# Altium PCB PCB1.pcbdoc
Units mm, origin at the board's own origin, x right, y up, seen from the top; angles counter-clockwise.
Board outline 153.8 x 97.66 mm, 2 copper layers (Top Layer, Bottom Layer); 80 components, 110 nets, 410 pads, 304 vias.
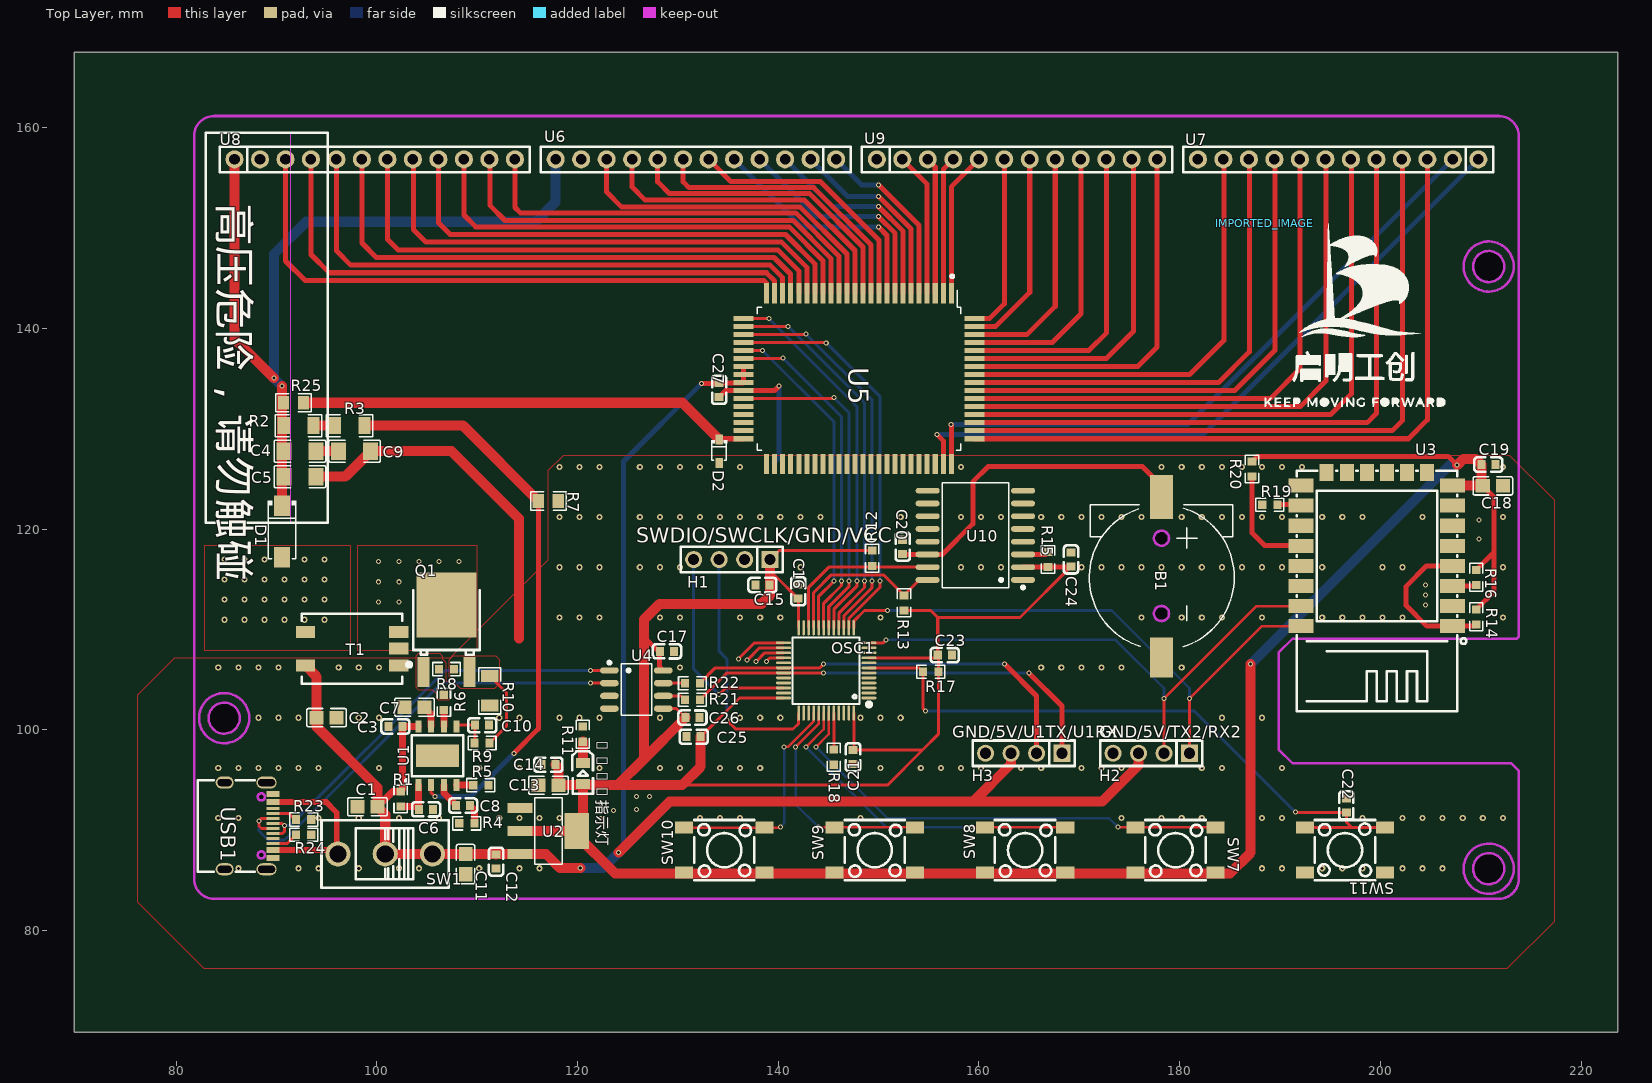
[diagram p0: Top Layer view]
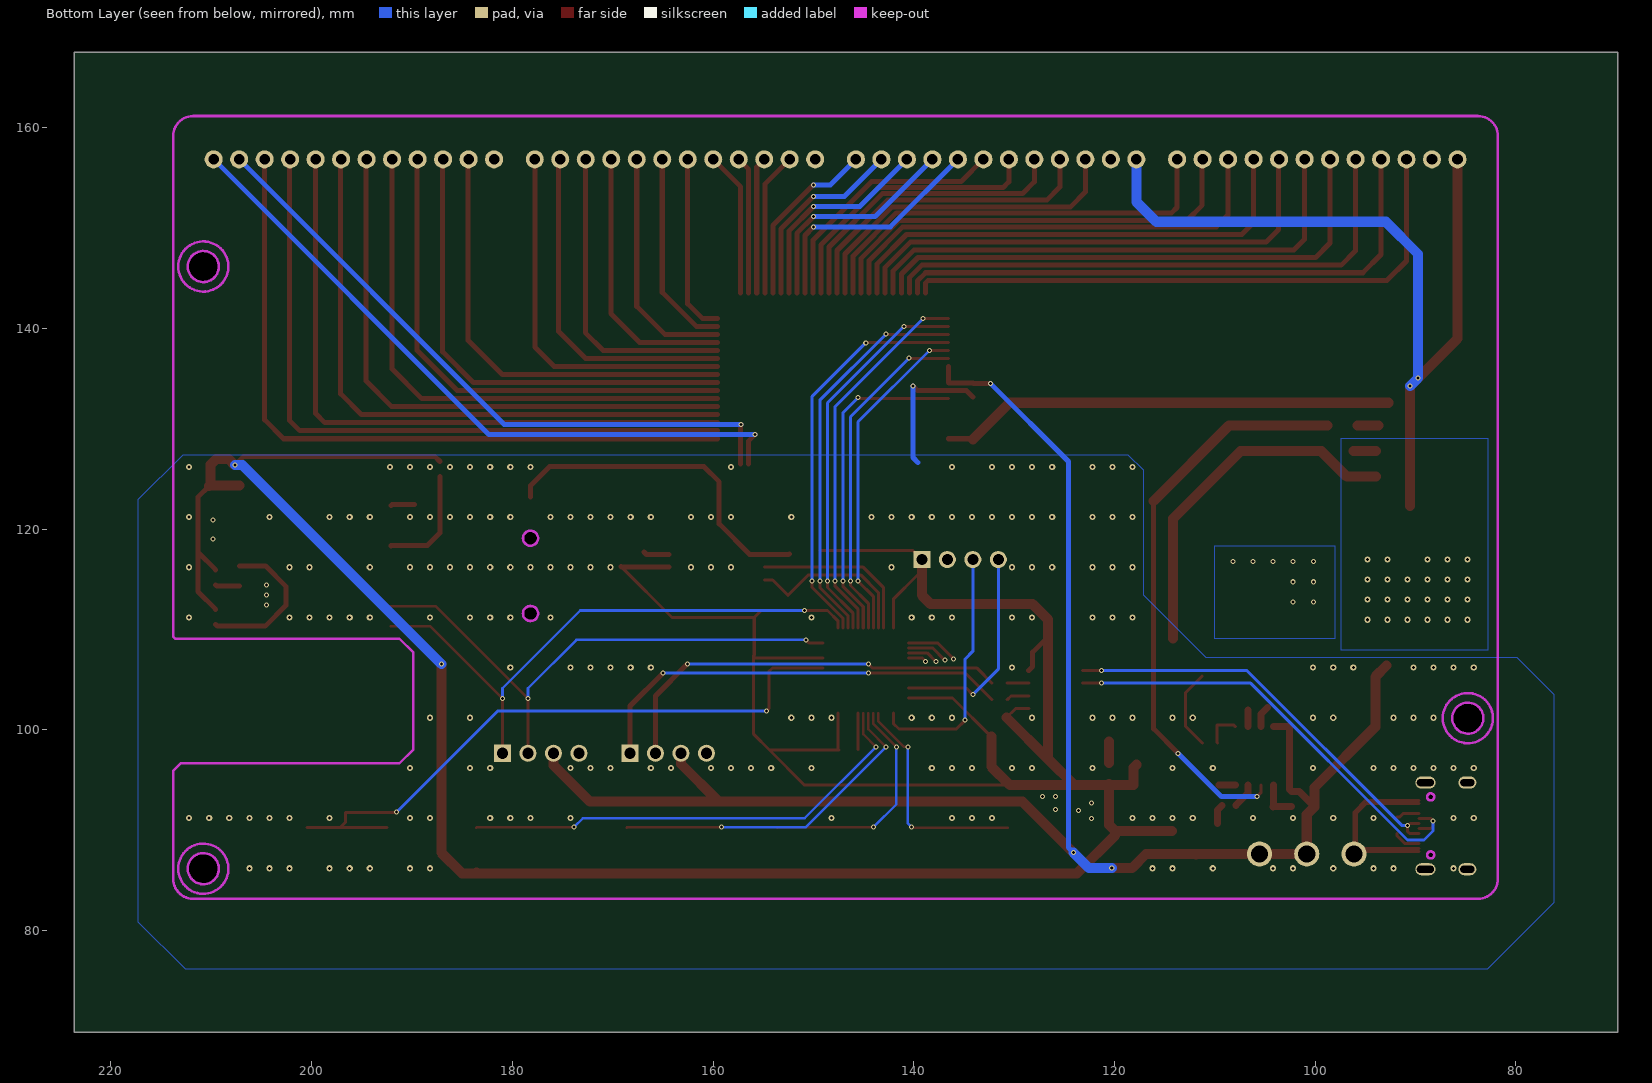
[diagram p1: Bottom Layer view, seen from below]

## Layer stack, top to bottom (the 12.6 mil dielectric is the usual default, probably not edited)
Top Layer: signal copper (thickness not stored)
Dielectric: dielectric 0.32, FR-4, Dk 4.8
Bottom Layer: signal copper (thickness not stored)

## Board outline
223.647,69.85 69.85,69.85 69.85,167.513 223.647,167.513
cut-out: 86.338,101.163 ccw(c84.788,101.151) 83.238,101.163 ccw(c84.788,101.175)
cut-out: 212.338,146.163 ccw(c210.788,146.151) 209.238,146.163 ccw(c210.788,146.175)
cut-out: 212.338,86.163 ccw(c210.788,86.151) 209.238,86.163 ccw(c210.788,86.175)

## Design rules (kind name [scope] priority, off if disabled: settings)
Clearance copperThickness1oz [All] p1: gap=0.178 ignorepadtopadclearanceinfootprint=FALSE except(0.102: Track-Track; 0.152: Track-SMDPad SMDPad-SMDPad Track-THPad SMDPad-THPad THPad-THPad Track-Via SMDPad-Via THPad-Via Via-Via Track-Fill SMDPad-Fill THPad-Fill Via-Fill Fill-Fill Track-Region SMDPad-Region THPad-Region Via-Region Fill-Region Region-Region Track-Poly SMDPad-Poly THPad-Poly Via-Poly Fill-Poly Region-Poly Poly-Poly Track-Text SMDPad-Text THPad-Text Via-Text Fill-Text Region-Text Poly-Text Text-Text Track-Hole SMDPad-Hole THPad-Hole Via-Hole Fill-Hole Region-Hole Poly-Hole Text-Hole; 0.3: Track-Sheet SMDPad-Sheet THPad-Sheet Via-Sheet Fill-Sheet Region-Sheet Poly-Sheet Text-Sheet Sheet-Hole)
Clearance copperThickness2oz [All] p1: gap=0.178 ignorepadtopadclearanceinfootprint=FALSE except(0.152: Track-SMDPad SMDPad-SMDPad Track-THPad SMDPad-THPad THPad-THPad Track-Via SMDPad-Via THPad-Via Via-Via Track-Fill SMDPad-Fill THPad-Fill Via-Fill Fill-Fill Track-Region SMDPad-Region THPad-Region Via-Region Fill-Region Region-Region Track-Poly SMDPad-Poly THPad-Poly Via-Poly Fill-Poly Region-Poly Poly-Poly Track-Text SMDPad-Text THPad-Text Via-Text Fill-Text Region-Text Poly-Text Text-Text Track-Hole SMDPad-Hole THPad-Hole Via-Hole Fill-Hole Region-Hole Poly-Hole Text-Hole; 0.203: Track-Track; 0.3: Track-Sheet SMDPad-Sheet THPad-Sheet Via-Sheet Fill-Sheet Region-Sheet Poly-Sheet Text-Sheet Sheet-Hole)
DiffPairsRouting differentialPair [All] p1: maxuncoupledlength=10 maxlimit=5.9843 mostfreqgap=5.9843 toplayer_minwidth=5 toplayer_prefwidth=10 toplayer_maxwidth=100 bottomlayer_minwidth=5 bottomlayer_prefwidth=10 bottomlayer_maxwidth=100
PasteMaskExpansion pasteMaskExpansion [All] p1:
PlaneConnect innerPlane [All] p1: planeconnectstyle=Relief reliefexpansion=0.508 reliefentries=4 reliefconductorwidth=0.254 reliefairgap=0.254
PolygonConnect copperRegion [All] p1: connectstyle=Direct reliefentries=4 reliefconductorwidth=10 polygonreliefangle="90 Angle" airgapwidth=10
RoutingVias viaSize [All] p1: viastyle="Through Hole" holewidth=12.0078 minholewidth=11.811 maxholewidth=248.0314 width=24.0158 minwidth=19.685 maxwidth=393.7008
SolderMaskExpansion solderMaskExpansion [All] p1: useseparateexpansions=TRUE expansion=2.0079 expansionbottom=2.0079
Width copperThickness1oz [All] p1: maxlimit=100 minlimit=5 preferedwidth=10
Width copperThickness2oz [All] p1: maxlimit=100 minlimit=8 preferedwidth=10

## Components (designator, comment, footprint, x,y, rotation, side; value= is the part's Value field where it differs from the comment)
3.3V指示灯 "NCD0805R1" LED0805-R-RD 120.523,95.631 r270 top
B1 "CR1220-2" BAT-SMD_CR1220-2 178.181,115.189 r270 top
C1 "0805X106K250NT" C0805 99.06,92.329 r0 top
C2 "0805X106K250NT" C0805 94.996,101.219 r180 top
C3 "0603B104K500NT" C0603 101.854,100.33 r0 top
C4 "CL31B105KCHNNNE" C1206 92.329,127.762 r180 top
C5 "1206B104K251NT_C2909525" C1206 92.329,125.222 r180 top
C6 "0603B104K500NT" C0603 104.902,92.075 r180 top
C7 "0805X106K250NT" C0805 103.759,102.235 r180 top
C8 "0603B103K500NT" C0603 108.585,92.456 r180 top
C9 "CL31B105KCHNNNE" C1206 97.79,127.762 r180 top
C10 "0603B104K500NT" C0603 110.49,100.457 r180 top
C11 "GRM21BR61H106KE43L" C0805 108.839,86.614 r90 top
C12 "0603B104K500NT" C0603 111.887,86.868 r90 top
C13 "GRM21BR61H106KE43L" C0805 117.094,94.488 r0 top
C14 "0603B104K500NT" C0603 117.094,96.52 r0 top
C15 "0603B104K500NT" C0603 138.43,114.427 r0 top
C16 "0603B104K500NT" C0603 141.986,113.792 r270 top
C17 "0603B104K500NT" C0603 128.905,107.823 r180 top
C18 "0805X106K250NT" C0805 211.201,124.301 r180 top
C19 "0603B104K500NT" C0603 210.758,126.427 r0 top
C20 "0603B104K500NT" C0603 152.4,118.237 r270 top
C21 "0603B104K500NT" C0603 147.447,97.282 r90 top
C22 "0603B105K250NT" C0603 196.596,92.456 r270 top
C23 "0603B104K500NT" C0603 156.591,107.442 r0 top
C24 "0603B104K500NT" C0603 169.164,116.967 r270 top
C25 "0603B104K500NT" C0603 131.572,99.314 r180 top
C26 "0603B104K500NT" C0603 131.445,101.219 r180 top
C27 "0603B104K500NT" C0603 134.112,133.858 r270 top
D1 "ES1J_C412438" SMA_L4.4-W2.8-LS5.4-RD 90.551,119.761 r270 top
D2 "MM3Z68_C118625" SOD-323_L1.8-W1.3-LS2.5-RD-1 134.112,127.762 r270 top
H1 "PZ254V-11-04P" HDR-TH_4P-P2.54-V-M 135.382,116.967 r180 top
H2 "PZ254V-11-04P" HDR-TH_4P-P2.54-V-M 177.165,97.663 r180 top
H3 "PZ254V-11-04P" HDR-TH_4P-P2.54-V-M 164.465,97.663 r180 top
IMPORTED_IMAGE "IMPORTED_IMAGE" IMPORTED_IMAGE 188.468,150.495 r0 top
OSC1 "STM32F103C8T6TR" LQFP-48_L7.0-W7.0-P0.50-LS9.0-BL 144.78,105.918 r90 top
Q1 "NCEP02515K" TO-252-3_L6.6-W6.1-P4.58-LS10.1-BR-2 106.934,109.093 r270 top
R1 "0603WAF1002T5E" R0603 102.371,93.1 r90 top
R2 "1206W4F1003T5E" R1206 92.202,130.302 r0 top
R3 "1206W4F1003T5E" R1206 97.282,130.302 r0 top
R4 "0603WAF1002T5E" R0603 108.966,90.678 r0 top
R5 "0603WAF2002T5E" R0603 110.363,94.488 r180 top
R6 "0603WAF0000T5E" R0603 106.68,102.743 r90 top
R7 "0805W8F1501T5E" R0805 117.094,122.809 r180 top
R8 "0603WAF1002T5E" R0603 106.934,106.045 r180 top
R9 "0603WAF200JT5E" R0603 110.49,98.679 r0 top
R10 "1206W4F100LT5E" R1206 111.252,103.886 r90 top
R11 "0603WAF1001T5E" R0603 120.523,99.568 r270 top
R12 "0603WAF1002T5E" R0603 149.352,117.094 r90 top
R13 "0603WAF1002T5E" R0603 152.527,112.649 r270 top
R14 "0603WAF1002T5E" R0603 209.55,111.252 r90 top
R15 "0603WAF1002T5E" R0603 166.878,116.967 r90 top
R16 "0603WAF1002T5E" R0603 209.55,115.189 r90 top
R17 "0603WAF1002T5E" R0603 155.194,105.791 r180 top
R18 "0603WAF1002T5E" R0603 145.533,97.273 r90 top
R19 "0603WAF1002T5E" R0603 188.976,122.428 r180 top
R20 "0603WAF1002T5E" R0603 187.198,125.984 r270 top
R21 "0603WAF0000T5E" R0603 131.445,102.997 r0 top
R22 "0603WAF0000T5E" R0603 131.445,104.648 r0 top
R23 "RC0603FR-071KL" R0603 92.71,91.059 r0 top
R24 "RC0603FR-071KL" R0603 92.71,89.535 r0 top
R25 "0805W8F2403T5E" R0805 91.694,132.588 r180 top
SW1 "SS-12D10L3" SW-TH_SS-12D10L3 100.838,87.63 r180 top
SW7 "TS-1102S-B-A-B" SW-SMD_4P-L6.0-W6.0-P4.50-LS8.6 179.578,88.011 r0 top
SW8 "TS-1102S-B-A-B" SW-SMD_4P-L6.0-W6.0-P4.50-LS8.6 164.592,88.011 r0 top
SW9 "TS-1102S-B-A-B" SW-SMD_4P-L6.0-W6.0-P4.50-LS8.6 149.606,88.011 r0 top
SW10 "TS-1102S-B-A-B" SW-SMD_4P-L6.0-W6.0-P4.50-LS8.6 134.62,88.011 r0 top
SW11 "TS-1102S-B-A-B" SW-SMD_4P-L6.0-W6.0-P4.50-LS8.6 196.469,88.011 r180 top
T1 "TTRN-060S-013-T" TTRN-060S-013 97.536,108.077 r90 top
U1 "ASP3756" ESOP-8_L4.9-W3.9-P1.27-LS6.0-BL-EP4.2 106.045,97.409 r0 top
U2 "AMS1117-3.3_C369933" SOT-223-4_L6.5-W3.5-P2.30-LS7.0-BR 117.094,89.916 r180 top
U3 "ESP-12F(ESP8266MOD)" WIFIM-SMD_ESP-12F-ESP8266MOD 199.644,117.983 r90 top
U4 "CH340N" SOP-8_L4.9-W3.9-P1.27-LS6.0-BL 125.857,104.013 r270 top
U5 "HV57708" PQFP-80_L20.0-W14.0-P0.80-LS23.2-BL 148.042,135.001 r180 top
U6 "KH-2.54FH-1X12P-H8.5" HDR-TH_12P-P2.54-V-F 131.788,156.845 r180 top
U7 "KH-2.54FH-1X12P-H8.5" HDR-TH_12P-P2.54-V-F 195.788,156.845 r180 top
U8 "KH-2.54FH-1X12P-H8.5" HDR-TH_12P-P2.54-V-F 99.788,156.845 r0 top
U9 "KH-2.54FH-1X12P-H8.5" HDR-TH_12P-P2.54-V-F 163.788,156.845 r0 top
U10 "DS3231SN#T&R" SOIC-16_L10.3-W7.5-P1.27-LS10.3-BL 159.639,119.38 r90 top
USB1 "KH-TYPE-C-16P" USB-C-SMD_KH-TYPE-C-16P 87.249,90.424 r270 top

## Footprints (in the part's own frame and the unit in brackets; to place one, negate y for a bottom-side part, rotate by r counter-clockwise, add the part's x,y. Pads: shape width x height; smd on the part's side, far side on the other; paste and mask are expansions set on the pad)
BAT-SMD_CR1220-2 [mm]
  rect 4.4x2.3 smd: 1(-8,0)
  rect 4x2.3 smd: 2(8,0)
  Multi-Layer board cut-out: 3.6,0.75 3.275,0.676 3.014,0.468 2.869,0.167 2.869,-0.167 3.014,-0.468 3.275,-0.676 3.6,-0.75 3.6,-0.75 3.925,-0.676 4.186,-0.468 4.331,-0.167 4.331,0.167 4.186,0.468 3.925,0.676 3.6,0.75
  Multi-Layer board cut-out: -3.9,0.75 -4.225,0.676 -4.486,0.468 -4.631,0.167 -4.631,-0.167 -4.486,-0.468 -4.225,-0.676 -3.9,-0.75 -3.9,-0.75 -3.574,-0.676 -3.314,-0.468 -3.169,-0.167 -3.169,0.167 -3.314,0.468 -3.574,0.676 -3.9,0.75
  Multi-Layer keep-out circle w0.254: c3.6,0 r0.75
  Multi-Layer keep-out circle w0.254: c-3.9,0 r0.75
  silkscreen extent -7.22,-7.19 6.92,7.25
C0603 [mm]
  rect 0.8x0.9 smd: 1(-0.7,0) 2(0.7,0)
  silkscreen extent -1.41,-0.71 1.39,0.72
C0805 [mm]
  rect 1.41x1.35 smd: 1(-1,0) 2(1,0)
  silkscreen extent -1.96,-0.9 1.96,0.9
C1206 [mm]
  rect 1.485x1.728 smd: 1(-1.593,0) 2(1.593,0)
  silkscreen extent -2.56,-1.09 2.56,1.09
ESOP-8_L4.9-W3.9-P1.27-LS6.0-BL-EP4.2 [mm]
  rect 0.6x1.2 smd: 1(-1.905,-2.908) 2(-0.635,-2.908) 3(0.635,-2.908) 4(1.905,-2.908) 5(1.905,2.908) 6(0.635,2.908) 7(-0.635,2.908) 8(-1.905,2.908)
  rect 4.25x2.25 smd: 9(0,0)
  silkscreen extent -3.2,-2.67 2.55,2.05
HDR-TH_4P-P2.54-V-M [mm]
  rect 1.7x1.7 hole 1.1: 1(-3.81,0)
  round 1.7 hole 1.1: 2(-1.27,0) 3(1.27,0) 4(3.81,0)
  silkscreen extent -5.08,-1.27 5.08,1.27
HDR-TH_12P-P2.54-V-F [mm]
  round 1.8 hole 1.05: 1(-13.97,0) 2(-11.43,0) 3(-8.89,0) 4(-6.35,0) 5(-3.81,0) 6(-1.27,0) 7(1.27,0) 8(3.81,0) 9(6.35,0) 10(8.89,0) 11(11.43,0) 12(13.97,0)
  silkscreen extent -15.45,-1.27 15.45,1.27
IMPORTED_IMAGE [mm]
  silkscreen extent 0,-18.31 18,0
LED0805-R-RD [mm]
  rect 1x1.4 smd: 1(1.05,0) 2(-1.05,0)
  silkscreen extent -2.22,-1.04 1.99,1.01
LQFP-48_L7.0-W7.0-P0.50-LS9.0-BL [mm]
  oval 0.27x1.5 smd: 1(-2.75,-4.25) 2(-2.25,-4.25) 3(-1.75,-4.25) 4(-1.25,-4.25) 5(-0.75,-4.25) 6(-0.25,-4.25) 7(0.25,-4.25) 8(0.75,-4.25) 9(1.25,-4.25) 10(1.75,-4.25) 11(2.25,-4.25) 12(2.75,-4.25) 25(2.75,4.25) 26(2.25,4.25) 27(1.75,4.25) 28(1.25,4.25) 29(0.75,4.25) 30(0.25,4.25) 31(-0.25,4.25) 32(-0.75,4.25) 33(-1.25,4.25) 34(-1.75,4.25) 35(-2.25,4.25) 36(-2.75,4.25)
  oval 1.5x0.27 smd: 13(4.25,-2.75) 14(4.25,-2.25) 15(4.25,-1.75) 16(4.25,-1.25) 17(4.25,-0.75) 18(4.25,-0.25) 19(4.25,0.25) 20(4.25,0.75) 21(4.25,1.25) 22(4.25,1.75) 23(4.25,2.25) 24(4.25,2.75) 37(-4.25,2.75) 38(-4.25,2.25) 39(-4.25,1.75) 40(-4.25,1.25) 41(-4.25,0.75) 42(-4.25,0.25) 43(-4.25,-0.25) 44(-4.25,-0.75) 45(-4.25,-1.25) 46(-4.25,-1.75) 47(-4.25,-2.25) 48(-4.25,-2.75)
  silkscreen extent -3.59,-4.46 3.3,3.34
PQFP-80_L20.0-W14.0-P0.80-LS23.2-BL [mm]
  rect 0.5x2 smd: 1(-9.2,-8.5) 2(-8.4,-8.5) 3(-7.6,-8.5) 4(-6.8,-8.5) 5(-6,-8.5) 6(-5.2,-8.5) 7(-4.4,-8.5) 8(-3.6,-8.5) 9(-2.8,-8.5) 10(-2,-8.5) 11(-1.2,-8.5) 12(-0.4,-8.5) 13(0.4,-8.5) 14(1.2,-8.5) 15(2,-8.5) 16(2.8,-8.5) 17(3.6,-8.5) 18(4.4,-8.5) 19(5.2,-8.5) 20(6,-8.5) 21(6.8,-8.5) 22(7.6,-8.5) 23(8.4,-8.5) 24(9.2,-8.5) 41(9.2,8.5) 42(8.4,8.5) 43(7.6,8.5) 44(6.8,8.5) 45(6,8.5) 46(5.2,8.5) 47(4.4,8.5) 48(3.6,8.5) 49(2.8,8.5) 50(2,8.5) 51(1.2,8.5) 52(0.4,8.5) 53(-0.4,8.5) 54(-1.2,8.5) 55(-2,8.5) 56(-2.8,8.5) 57(-3.6,8.5) 58(-4.4,8.5) 59(-5.2,8.5) 60(-6,8.5) 61(-6.8,8.5) 62(-7.6,8.5) 63(-8.4,8.5) 64(-9.2,8.5)
  rect 2x0.5 smd: 25(11.5,-6) 26(11.5,-5.2) 27(11.5,-4.4) 28(11.5,-3.6) 29(11.5,-2.8) 30(11.5,-2) 31(11.5,-1.2) 32(11.5,-0.4) 33(11.5,0.4) 34(11.5,1.2) 35(11.5,2) 36(11.5,2.8) 37(11.5,3.6) 38(11.5,4.4) 39(11.5,5.2) 40(11.5,6) 65(-11.5,6) 66(-11.5,5.2) 67(-11.5,4.4) 68(-11.5,3.6) 69(-11.5,2.8) 70(-11.5,2) 71(-11.5,1.2) 72(-11.5,0.4) 73(-11.5,-0.4) 74(-11.5,-1.2) 75(-11.5,-2) 76(-11.5,-2.8) 77(-11.5,-3.6) 78(-11.5,-4.4) 79(-11.5,-5.2) 80(-11.5,-6)
  silkscreen extent -10.12,-10.35 10.12,7.13
R0603 [mm]
  rect 0.806x0.864 smd: 1(-0.753,0) 2(0.753,0)
  silkscreen extent -1.39,-0.66 1.39,0.66
R0805 [mm]
  rect 1.133x1.377 smd: 1(-1,0) 2(1,0)
  silkscreen extent -1.76,-0.92 1.76,0.92
R1206 [mm]
  rect 1.208x1.701 smd: 1(-1.479,0) 2(1.479,0)
  silkscreen extent -2.31,-1.08 2.31,1.08
SMA_L4.4-W2.8-LS5.4-RD [mm]
  rect 2.046x1.62 smd: 1(-2.565,0) 2(2.565,0)
  silkscreen extent -3.08,-1.44 2.7,1.44
SOD-323_L1.8-W1.3-LS2.5-RD-1 [mm]
  rect 1x0.75 smd: 1(-1.173,0) 2(1.173,0)
  silkscreen extent -1.08,-0.8 0.9,0.8
SOIC-16_L10.3-W7.5-P1.27-LS10.3-BL [mm]
  oval 0.574x2.401 smd: 1(-4.445,-4.75) 2(-3.175,-4.75) 3(-1.905,-4.75) 4(-0.635,-4.75) 5(0.635,-4.75) 6(1.905,-4.75) 7(3.175,-4.75) 8(4.445,-4.75) 9(4.445,4.75) 10(3.175,4.75) 11(1.905,4.75) 12(0.635,4.75) 13(-0.635,4.75) 14(-1.905,4.75) 15(-3.175,4.75) 16(-4.445,4.75)
  silkscreen extent -5.33,-4.9 5.23,3.32
SOP-8_L4.9-W3.9-P1.27-LS6.0-BL [mm]
  oval 0.63x1.865 smd: 1(-1.905,-2.682) 2(-0.635,-2.682) 3(0.635,-2.682) 4(1.905,-2.682) 5(1.905,2.682) 6(0.635,2.682) 7(-0.635,2.682) 8(-1.905,2.682)
  silkscreen extent -2.82,-2.83 2.58,1.52
SOT-223-4_L6.5-W3.5-P2.30-LS7.0-BR [mm]
  rect 2.47x0.98 smd: 1(2.835,-2.3) 2(2.835,0) 3(2.835,2.3)
  rect 2.47x3.6 smd: 4(-2.835,0)
  silkscreen extent -1.37,-3.33 1.37,3.33
SW-SMD_4P-L6.0-W6.0-P4.50-LS8.6 [mm]
  rect 1.8x1.2 smd: 1(-4,2.25) 2(4,2.25) 3(-4,-2.25) 4(4,-2.25)
  silkscreen extent -3,-3 3,3
SW-TH_SS-12D10L3 [mm]
  round 2.5 hole 1.7: 1(-4.7,0) 2(0,0) 3(4.7,0)
  silkscreen extent -6.35,-3.35 6.35,3.35
TO-252-3_L6.6-W6.1-P4.58-LS10.1-BR-2 [mm]
  rect 3x1.2 smd: 1(3.342,-2.285) 3(3.342,2.285)
  rect 6.5x6 smd: 2(-3.343,0)
  silkscreen extent -4.83,-3.92 2.81,3.3
TTRN-060S-013 [mm]
  rect 1.2x1.9 smd: 1(-1.675,4.65) 2(1.675,4.651) 3(-1.675,-4.65) 5(1.675,-4.651)
  rect 1.15x1.9 smd: EMPTY(0.025,-4.65)
  silkscreen extent -3.5,-5 3.5,5
USB-C-SMD_KH-TYPE-C-16P [mm]
  oval 1.2x2 hole 0.7 slot 1.7 at 90 deg: 1(-4.32,1.765) 2(4.32,1.765)
  oval 1.2x1.8 hole 0.7 slot 1.4 at 90 deg: 3(-4.32,-2.415) 4(4.32,-2.415)
  rect 0.3x1.3 smd: A1(-3.35,2.415) A4(-2.55,2.415) A5(-1.25,2.415) A6(-0.25,2.415) A7(0.25,2.415) A8(1.25,2.415) A9(2.55,2.415) A12(3.35,2.415) B1(3.05,2.415) B4(2.25,2.415) B5(1.75,2.415) B6(0.75,2.415) B7(-0.75,2.415) B8(-1.75,2.415) B9(-2.25,2.415) B12(-3.05,2.415)
  Multi-Layer board cut-out: -2.89,1.585 -3.042,1.55 -3.164,1.453 -3.231,1.313 -3.231,1.157 -3.164,1.017 -3.042,0.92 -2.89,0.885 -2.89,0.885 -2.738,0.92 -2.616,1.017 -2.549,1.157 -2.549,1.313 -2.616,1.453 -2.738,1.55 -2.89,1.585
  Multi-Layer board cut-out: 2.89,1.585 2.738,1.55 2.616,1.453 2.549,1.313 2.549,1.157 2.616,1.017 2.738,0.92 2.89,0.885 2.89,0.885 3.042,0.92 3.164,1.017 3.231,1.157 3.231,1.313 3.164,1.453 3.042,1.55 2.89,1.585
  Multi-Layer keep-out circle w0.254: c-2.89,1.235 r0.35
  Multi-Layer keep-out circle w0.254: c2.89,1.235 r0.35
  silkscreen extent -4.57,-5.08 4.57,0.57
WIFIM-SMD_ESP-12F-ESP8266MOD [mm]
  rect 1.4x2.5 smd: 1(-7.651,-7.551) 2(-5.651,-7.551) 3(-3.651,-7.551) 4(-1.651,-7.551) 5(0.349,-7.551) 6(2.349,-7.551) 7(4.349,-7.551) 8(6.349,-7.551) 9(6.349,7.549) 10(4.349,7.55) 11(2.349,7.551) 12(0.349,7.551) 13(-1.651,7.55) 14(-3.651,7.551) 15(-5.651,7.55) 16(-7.651,7.551)
  rect 1.7x1.4 smd: 17(7.651,-5) 18(7.649,-3.002) 19(7.65,-1.003) 20(7.65,0.997) 21(7.65,2.997) 22(7.65,4.997)
  silkscreen extent -16.15,-8.92 7.85,8

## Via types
v1: diameter 0.61, hole 0.304, Top Layer to Bottom Layer, 225 vias
v2: diameter 0.5, hole 0.3, Top Layer to Bottom Layer, 79 vias

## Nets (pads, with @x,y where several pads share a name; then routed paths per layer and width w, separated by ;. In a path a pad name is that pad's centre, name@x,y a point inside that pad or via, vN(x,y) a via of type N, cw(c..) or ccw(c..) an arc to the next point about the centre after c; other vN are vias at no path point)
$2N14740: 3.3V指示灯.2 R11.2 | length 2.1
  Top Layer w1: 3.3V指示灯.2 R11.2
$2N61129: C6.2 R1.1 U1.1 | length 4
  Top Layer w0.69: R1.1 C6.2@104.185,92.346 ; U1.1 104.14,92.391 C6.2@104.185,92.346 ; C6.2@104.202,92.329 C6.2@104.185,92.346
$2N61132: C8.2 U1.3 | length 2.5
  Top Layer w0.69: U1.3 106.68,93.711 107.885,92.506 C8.2
$2N61133: C8.1 R4.2 | length 2
  Top Layer w0.69: C8.1 109.719,92.022 R4.2
$2N61134: R5.2 U1.4 | length 1.7
  Top Layer w0.69: U1.4 107.963,94.488 R5.2
$2N61136: C7.1 U1.7 | length 2.2
  Top Layer w0.69: C7.1 105.41,101.584 U1.7
$2N61143: C10.2 R9.1 U1.5 | length 3.7
  Top Layer w0.3: U1.5 108.09,100.457 C10.2 109.79,98.732 R9.1
$2N61144: R6.1 U1.6 | length 1.7
  Top Layer w0.69: U1.6 R6.1
$2N61145: Q1.1 R6.2 R8.2
$2N61146: R2.2 R3.1 | length 2.1
  Top Layer w1: R2.2 R3.1
$2N61148: Q1.3 R8.1 R9.2 R10.2 | length 8.1
  Top Layer w0.3: R9.2 112.903,100.339 112.903,103.714 R10.2
$2N61152: D1.2 T1.2
  other v1: 84.804,110.966 86.804,110.966 88.804,110.966 90.804,110.966 92.804,110.966 94.804,110.966 84.804,112.966 86.804,112.966 88.804,112.966 90.804,112.966 92.804,112.966 94.804,112.966 84.804,114.966 86.804,114.966 88.804,114.966 90.804,114.966 92.804,114.966 94.804,114.966 84.804,116.966 86.804,116.966 88.804,116.966 92.804,116.966 94.804,116.966
$2N61153: Q1.2 T1.5
  other v2: 100.187,112.752 102.187,112.752 100.187,114.752 102.187,114.752 100.187,116.752 102.187,116.752 104.187,116.752 106.187,116.752 108.187,116.752
$2N62507: C4.1 C9.2 | length 2.3
  Top Layer w1: C4.1 C9.2
$4N23212: R15.2 U10.3 | length 2.6
  Top Layer w0.5: U10.3 166.633,117.475 R15.2
$4N37986: R22.1 U4.7 | length 2.2
  Top Layer w0.3: U4.7 R22.1
$4N37987: R21.1 U4.6 | length 2.3
  Top Layer w0.3: U4.6 130.311,103.378 R21.1
$4N48239: B1.1 C20.2 U10.14 | length 33.8
  Top Layer w0.5: C20.2 152.462,117.475 U10.14 156.339,117.475 159.385,120.521 159.385,124.714 160.909,126.238 176.276,126.238 178.181,124.333 B1.1
$4N60541: R16.1 U3.3 | length 2.4
  Top Layer w0.5: U3.3 209.447,114.332 R16.1
$4N60605: R19.1 U3.10 | length 2.4
  Top Layer w0.5: R19.1 191.998,122.428 U3.10
$4N60656: R20.2 U3.12 | length 11
  Top Layer w0.5: R20.2 187.198,119.634 188.468,118.364 192.062,118.364 U3.12
$7N2158: D2.1 R25.1 U5.40 | length 45.4
  Top Layer w0.5: D2.1 134.178,129.001 U5.40
  Top Layer w1: R25.1 130.459,132.588 D2.1
BOOT0: OSC1.44 R18.2 | length 3.6
  Top Layer w0.3: OSC1.44 145.53,98.03 R18.2
DS_SCL: OSC1.21 R13.1 U10.16 | length 17.1
  Top Layer w0.3: OSC1.21 143.53,113.685 145.288,115.443 150.486,115.443 R13.1 154.06,114.935 U10.16
DS_SDA: OSC1.22 R12.1 U10.15 | length 16.7
  Top Layer w0.3: OSC1.22 143.03,114.201 145.034,116.205 U10.15
ESP_RST: R14.1 U3.1 U3.4 | length 15.3
  Top Layer w0.5: U3.4 204.597,116.332 202.565,114.3 202.565,112.395 204.628,110.332 U3.1 209.384,110.332 R14.1
FB: R3.2 R7.2 U1.2 | length 57.6
  Top Layer w0.3: U1.2 105.41,93.726 v2(105.791,93.345)
  Top Layer w0.5: v2(113.665,97.663) 116.094,100.092 R7.2
  Top Layer w1: R3.2 108.601,130.302 R7.2
  Bottom Layer w0.5: v2(105.791,93.345) 109.347,93.345 v2(113.665,97.663)
G1_0: U5.24 U8.3 | length 60
  Top Layer w0.5: U8.3 90.898,146.719 92.837,144.78 138.557,144.78 138.842,144.495 U5.24
G1_1: U5.23 U8.4 | length 58
  Top Layer w0.5: U8.4 93.438,147.354 95.25,145.542 138.811,145.542 139.642,144.711 U5.23
G1_2: U5.22 U8.5 | length 56.2
  Top Layer w0.5: U8.5 95.978,147.735 97.409,146.304 139.192,146.304 140.442,145.054 U5.22
G1_3: U5.21 U8.6 | length 54.3
  Top Layer w0.5: U8.6 98.518,148.497 99.949,147.066 139.573,147.066 141.224,145.415 141.224,143.519 U5.21
G1_4: U5.20 U8.7 | length 52.5
  Top Layer w0.5: U8.7 101.058,148.878 102.108,147.828 139.954,147.828 142.042,145.74 U5.20
G1_5: U5.19 U8.8 | length 50.4
  Top Layer w0.5: U8.8 103.632,156.811 103.632,149.86 104.902,148.59 140.335,148.59 142.842,146.083 U5.19
G1_6: U5.18 U8.9 | length 48.4
  Top Layer w0.5: U8.9 106.138,150.529 107.315,149.352 140.716,149.352 143.642,146.426 U5.18
G1_7: U5.17 U8.10 | length 46.5
  Top Layer w0.5: U8.10 108.678,151.291 109.855,150.114 141.097,150.114 144.442,146.769 U5.17
G1_8: U5.16 U8.11 | length 44.3
  Top Layer w0.5: U8.11 111.252,156.811 111.252,152.273 112.776,150.749 141.478,150.749 145.242,146.985 U5.16
G1_9: U5.15 U8.12 | length 42.8
  Top Layer w0.5: U8.12 113.758,152.053 114.3,151.511 141.732,151.511 146.042,147.201 U5.15
G2_0: U5.14 U6.10 | length 33.7
  Top Layer w0.5: U6.10 122.898,153.581 124.366,152.113 142.146,152.113 146.842,147.417 U5.14
G2_1: U5.13 U6.9 | length 31.8
  Top Layer w0.5: U6.9 125.438,154.089 126.746,152.781 142.621,152.781 147.642,147.76 U5.13
G2_2: U5.12 U6.8 | length 30
  Top Layer w0.5: U6.8 127.978,154.597 129.159,153.416 143.129,153.416 148.442,148.103 U5.12
G2_3: U5.11 U6.7 | length 28.4
  Top Layer w0.5: U6.7 130.518,154.597 131.097,154.018 143.543,154.018 149.242,148.319 U5.11
G2_4: U5.10 U6.6 | length 25.6
  Top Layer w0.5: U6.6 135.283,154.62 144.211,154.62 150.042,148.789 U5.10
G2_5: U5.9 U6.5 | length 24.1
  Top Layer w0.5: v2(149.987,150.114) 150.842,149.259 U5.9
  Bottom Layer w0.5: U6.5 142.329,150.114 v2(149.987,150.114)
G2_6: U5.8 U6.4 | length 22.5
  Top Layer w0.5: v2(149.987,151.13) 151.642,149.475 U5.8
  Bottom Layer w0.5: U6.4 143.853,151.13 v2(149.987,151.13)
G2_7: U5.7 U6.3 | length 20.9
  Top Layer w0.5: v2(149.987,152.146) 152.442,149.691 U5.7
  Bottom Layer w0.5: U6.3 145.377,152.146 v2(149.987,152.146)
G2_8: U5.6 U6.2 | length 19.3
  Top Layer w0.5: v2(149.987,153.162) 153.242,149.907 U5.6
  Bottom Layer w0.5: U6.2 146.901,153.162 v2(149.987,153.162)
G2_9: U5.5 U6.1 | length 17.8
  Top Layer w0.5: v2(149.987,154.305) 154.042,150.25 U5.5
  Bottom Layer w0.5: U6.1 148.298,154.305 v2(149.987,154.305)
G3_0: U5.4 U9.2 | length 14.4
  Top Layer w0.5: U9.2 154.842,154.361 U5.4
G3_1: U5.3 U9.3 | length 13.7
  Top Layer w0.5: U9.3 155.642,156.101 U5.3
G3_2: U5.2 U9.4 | length 13.8
  Top Layer w0.5: U5.2 156.442,155.849 U9.4
G3_3: U5.1 U9.5 | length 14.5
  Top Layer w0.5: U5.1 157.242,154.109 U9.5
G3_4: U5.80 U9.6 | length 18
  Top Layer w0.5: U5.80 161.067,141.001 162.518,142.452 U9.6
G3_5: U5.79 U9.7 | length 20.2
  Top Layer w0.5: U5.79 161.664,140.201 165.058,143.595 U9.7
G3_6: U5.78 U9.8 | length 23.9
  Top Layer w0.5: U5.78 164.801,139.401 167.598,142.198 U9.8
G3_7: U5.77 U9.9 | length 27.2
  Top Layer w0.5: U5.77 167.303,138.601 170.18,141.478 170.18,156.803 U9.9
G3_8: U5.76 U9.10 | length 31.2
  Top Layer w0.5: U5.76 170.948,137.801 172.72,139.573 172.72,156.803 U9.10
G3_9: U5.75 U9.11 | length 34.2
  Top Layer w0.5: U5.75 172.688,137.001 175.387,139.7 175.387,156.676 U9.11
G4_0: U5.72 U7.10 | length 47.9
  Top Layer w0.5: U5.72 183.877,134.601 186.944,137.668 186.944,156.799 U7.10
G4_1: U5.71 U7.9 | length 50.7
  Top Layer w0.5: U5.71 185.49,133.801 189.484,137.795 189.484,156.799 U7.9
G4_2: U5.70 U7.8 | length 54.5
  Top Layer w0.5: U5.70 189.008,133.001 191.978,135.971 U7.8
G4_3: U5.69 U7.7 | length 58.2
  Top Layer w0.5: U5.69 192.018,132.201 194.564,134.747 194.564,156.799 U7.7
G4_4: U5.68 U7.6 | length 61.8
  Top Layer w0.5: U5.68 195.028,131.401 197.104,133.477 197.104,156.799 U7.6
G4_5: U5.67 U7.5 | length 65.8
  Top Layer w0.5: U5.67 198.673,130.601 199.598,131.526 U7.5
G4_6: U5.66 U7.4 | length 69.1
  Top Layer w0.5: U5.66 201.175,129.801 202.184,130.81 202.184,156.799 U7.4
G4_7: U5.65 U7.3 | length 71.9
  Top Layer w0.5: U5.65 202.788,129.001 204.678,130.891 U7.3
G4_8: U5.64 U7.2 | length 64.9
  Top Layer w0.5: v2(157.226,130.429) 157.242,130.413 U5.64
  Bottom Layer w0.5: v2(157.226,130.429) 180.802,130.429 U7.2
G4_9: U5.63 U7.1 | length 68.5
  Top Layer w0.5: v2(155.829,129.413) 156.442,128.8 U5.63
  Bottom Layer w0.5: v2(155.829,129.413) 182.326,129.413 U7.1
GND: B1.2 C1.1 C2.1 C3.1 C5.1 C6.1 C7.2 C9.1 C10.1 C11.1 C12.1 C13.1 C14.1 C15.1 C16.1 C17.1 C18.1 C19.2 C20.1 C21.1 C22.1 C23.2 C24.1 C25.2 C26.1 C27.2 D2.2 H1.2 H2.4 H3.4 OSC1.8 OSC1.23 OSC1.35 OSC1.47 R4.1 R5.1 R7.1 R10.1 R11.1 R18.1 R19.2 R23.2 R24.2 SW11.1 SW11.2 T1.3 U1.9 U2.1 U3.9 U4.3 U5.34 U10.13 USB1.1 USB1.2 USB1.3 USB1.4 USB1.A1 USB1.A12 USB1.B1 USB1.B12 | length 50.3
  Top Layer w0.5: C27.2 134.755,133.801 U5.34 139.643,133.801 v2(140.081,134.239)
  Top Layer w1: C5.1 96.843,125.222 C9.1 107.442,127.762 114.173,121.031 114.173,109.093
  Bottom Layer w0.5: 139.573,126.619 140.081,127.127 v2(140.081,134.239)
  other v1: 86.2,86.2 92.2,86.2 94.2,86.2 98.2,86.2 102.2,86.2 104.2,86.2 110.2,86.2 114.2,86.2 116.2,86.2 188.2,86.2 190.2,86.2 194.2,86.2 196.2,86.2 198.2,86.2 202.2,86.2 204.2,86.2 206.2,86.2 84.2,91.2 86.2,91.2 94.2,91.2 98.2,91.2 102.2,91.2 106.2,91.2 112.2,91.2 114.2,91.2 116.2,91.2 118.2,91.2 132.2,91.2 134.2,91.2 136.2,91.2 148.2,91.2 174.2,91.2 178.2,91.2 180.2,91.2 182.2,91.2 188.2,91.2 190.2,91.2 198.2,91.2 202.2,91.2 204.2,91.2 206.2,91.2 208.2,91.2 210.2,91.2 212.2,91.2 84.2,96.2 86.2,96.2 88.2,96.2 90.2,96.2 92.2,96.2 94.2,96.2 100.2,96.2 110.2,96.2 114.2,96.2 122.2,96.2 128.2,96.2 130.2,96.2 134.2,96.2 136.2,96.2 138.2,96.2 150.2,96.2 154.2,96.2 156.2,96.2 158.2,96.2 160.2,96.2 164.2,96.2 166.2,96.2 170.2,96.2 172.2,96.2 174.2,96.2 182.2,96.2 184.2,96.2 190.2,96.2 88.2,101.2 90.2,101.2 92.2,101.2 98.2,101.2 100.2,101.2 112.2,101.2 114.2,101.2 118.2,101.2 120.2,101.2 122.2,101.2 128.2,101.2 136.2,101.2 138.2,101.2 140.2,101.2 148.2,101.2 150.2,101.2 152.2,101.2 184.2,101.2 188.2,101.2 84.2,106.2 86.2,106.2 88.2,106.2 90.2,106.2 96.2,106.2 98.2,106.2 100.2,106.2 130.2,106.2 166.2,106.2 168.2,106.2 170.2,106.2 172.2,106.2 174.2,106.2 180.2,106.2 118.2,111.2 120.2,111.2 122.2,111.2 128.2,111.2 130.2,111.2 136.2,111.2 138.2,111.2 140.2,111.2 150.2,111.2 176.2,111.2 180.2,111.2 182.2,111.2 184.2,111.2 188.2,111.2 194.2,111.2 196.2,111.2 198.2,111.2 200.2,111.2 202.2,111.2 212.2,111.2 118.2,116.2 120.2,116.2 122.2,116.2 126.2,116.2 128.2,116.2 130.2,116.2 142.2,116.2 158.2,116.2 160.2,116.2 162.2,116.2 170.2,116.2 172.2,116.2 174.2,116.2 176.2,116.2 178.2,116.2 180.2,116.2 182.2,116.2 184.2,116.2 186.2,116.2 188.2,116.2 190.2,116.2 194.2,116.2 200.2,116.2 202.2,116.2 212.2,116.2 118.2,121.2 120.2,121.2 122.2,121.2 126.2,121.2 128.2,121.2 130.2,121.2 132.2,121.2 134.2,121.2 136.2,121.2 138.2,121.2 140.2,121.2 142.2,121.2 144.2,121.2 152.2,121.2 158.2,121.2 160.2,121.2 162.2,121.2 166.2,121.2 168.2,121.2 170.2,121.2 172.2,121.2 174.2,121.2 176.2,121.2 180.2,121.2 182.2,121.2 184.2,121.2 186.2,121.2 188.2,121.2 190.2,121.2 194.2,121.2 196.2,121.2 198.2,121.2 204.2,121.2 212.2,121.2 118.2,126.2 120.2,126.2 122.2,126.2 126.2,126.2 128.2,126.2 130.2,126.2 132.2,126.2 136.2,126.2 158.2,126.2 178.2,126.2 180.2,126.2 182.2,126.2 184.2,126.2 186.2,126.2 188.2,126.2 190.2,126.2 192.2,126.2 212.2,126.2
  other v2: 122.301,91.186 123.571,91.948 125.857,92.075 122.301,92.697 125.857,93.345 127.187,93.345 204.47,112.447 204.47,113.411 204.47,114.427 209.804,119.011 209.804,120.904
HGD_1: U5.74 U9.12 | length 37.7
  Top Layer w0.5: U5.74 175.825,136.201 177.758,138.134 U9.12
HGD_2: U5.73 U7.11 | length 44.3
  Top Layer w0.5: U5.73 180.994,135.401 184.404,138.811 184.404,156.799 U7.11
HV: C4.2 C5.2 D1.1 R2.1 R25.2 U6.12 U8.1 | length 83.3
  Top Layer w1: U8.1 85.818,138.972 v2(89.757,135.033) ; D1.1 v2(90.551,134.239)
  Bottom Layer w1: v2(90.551,134.239) v2(89.757,135.033) 89.757,147.415 92.964,150.622 115.824,150.622 117.818,152.616 U6.12
HV_CLK: OSC1.19 U5.30 | length 34
  Top Layer w0.3: U5.30 140.43,137.001 v2(140.462,137.033) ; OSC1.19 144.53,112.61 146.304,114.384 v2(146.304,114.808)
  Bottom Layer w0.3: v2(140.462,137.033) 146.304,131.191 v2(146.304,114.808)
HV_DIN1: OSC1.14 U5.28 | length 40.1
  Top Layer w0.3: U5.28 144.736,138.601 v2(144.78,138.557) ; OSC1.14 147.03,111.089 150.114,114.173 v2(150.114,114.808)
  Bottom Layer w0.3: v2(144.78,138.557) 150.114,133.223 v2(150.114,114.808)
HV_DIN2: OSC1.15 U5.27 | length 39.4
  Top Layer w0.3: U5.27 142.703,139.401 v2(142.748,139.446) ; OSC1.15 146.53,111.351 149.352,114.173 v2(149.352,114.808)
  Bottom Layer w0.3: v2(142.748,139.446) 149.352,132.842 v2(149.352,114.808)
HV_DIN3: OSC1.16 U5.26 | length 38.7
  Top Layer w0.3: U5.26 140.963,140.201 v2(140.97,140.208) ; OSC1.16 146.03,111.613 148.59,114.173 v2(148.59,114.808)
  Bottom Layer w0.3: v2(140.97,140.208) 148.59,132.588 v2(148.59,114.808)
HV_DIN4: OSC1.17 U5.25 | length 37.9
  Top Layer w0.3: U5.25 139.034,141.001 v2(139.065,140.97) ; OSC1.17 145.53,112.002 147.828,114.3 v2(147.828,114.808)
  Bottom Layer w0.3: v2(139.065,140.97) 147.828,132.207 v2(147.828,114.808)
HV_LE: OSC1.20 U5.29 | length 33.1
  Top Layer w0.3: U5.29 138.424,137.801 v2(138.43,137.795) ; OSC1.20 144.03,113.296 v2(145.542,114.808)
  Bottom Layer w0.3: v2(138.43,137.795) 145.542,130.683 v2(145.542,114.808)
HV_POL: OSC1.18 U5.35 | length 33.4
  Top Layer w0.3: U5.35 145.447,133.001 v2(145.542,133.096) ; OSC1.18 145.03,112.264 147.066,114.3 v2(147.066,114.808)
  Bottom Layer w0.3: v2(145.542,133.096) 147.066,131.572 v2(147.066,114.808)
NRST: C22.2 OSC1.7 R17.2 SW11.3 SW11.4 | length 65.4
  Top Layer w0.3: OSC1.7 154.064,106.168 R17.2 154.441,102.099 v2(154.686,101.854) ; v2(191.516,91.821) 191.581,91.756 C22.2 196.596,90.805 197.14,90.261 ; SW11.4 197.14,90.261 ; SW11.3 197.14,90.261
  Bottom Layer w0.3: v2(154.686,101.854) 181.483,101.854 v2(191.516,91.821)
PA0: OSC1.10
PA1: OSC1.11
PA2/U2TX: H2.2 OSC1.12 U3.15 | length 55.5
  Top Layer w0.254: H2.2 v2(178.435,103.124) 187.643,112.332 U3.15
  Top Layer w0.3: OSC1.12 150.451,108.668 v2(150.749,108.966)
  Bottom Layer w0.254: v2(150.749,108.966) 173.609,108.966 178.435,104.14 v2(178.435,103.124)
PA3/U2RX: H2.1 OSC1.13 U3.16 | length 58.3
  Top Layer w0.254: H2.1 v2(180.975,103.124) 188.183,110.332 U3.16
  Top Layer w0.3: OSC1.13 147.53,110.827 148.59,111.887 v2(150.876,111.887)
  Bottom Layer w0.254: v2(150.876,111.887) 173.228,111.887 180.975,104.14 v2(180.975,103.124)
PA8: OSC1.29
PA9/U1TX: H3.2 OSC1.30 R22.2 | length 41.4
  Top Layer w0.3: R22.2 133.722,106.172 140.526,106.172 OSC1.30 144.141,106.168 v2(144.526,106.553)
  Top Layer w0.5: v2(162.56,106.553) 165.735,103.378 H3.2
  Bottom Layer w0.3: v2(144.526,106.553) v2(162.56,106.553)
PA10/U1RX: H3.1 OSC1.31 R21.2 | length 43.3
  Top Layer w0.3: R21.2 134.869,105.668 OSC1.31 v2(144.526,105.668)
  Top Layer w0.5: v2(164.973,105.668) 168.275,102.366 H3.1
  Bottom Layer w0.3: v2(144.526,105.668) v2(164.973,105.668)
PA11: OSC1.32
PA12: OSC1.33
PA15: OSC1.38
PB3: OSC1.39
PB4: OSC1.40 SW10.1 SW10.2 | length 22.6
  Top Layer w0.254: SW10.1 SW10.2 140.172,90.261 v2(140.208,90.297) ; v2(140.589,98.298) 140.983,98.298 143.53,100.845 OSC1.40
  Bottom Layer w0.254: v2(140.208,90.297) 140.589,90.678 v2(140.589,98.298)
PB5: OSC1.41 SW9.1 SW9.2 | length 22.9
  Top Layer w0.254: v2(141.732,98.298) 144.03,100.596 OSC1.41 ; v2(144.018,90.297) 153.57,90.297 SW9.2
  Bottom Layer w0.254: v2(141.732,98.298) 141.732,92.583 v2(144.018,90.297)
PB6: OSC1.42 SW8.1 SW8.2 | length 33.3
  Top Layer w0.254: v2(142.748,98.298) 144.53,100.08 OSC1.42 ; v2(159.131,90.297) 168.556,90.297 SW8.2
  Bottom Layer w0.254: v2(142.748,98.298) 150.749,90.297 v2(159.131,90.297)
PB7: OSC1.43 SW7.1 SW7.2 | length 47
  Top Layer w0.254: v2(143.764,98.298) 145.03,99.564 OSC1.43 ; v2(173.863,90.297) 183.542,90.297 SW7.2
  Bottom Layer w0.254: v2(143.764,98.298) 150.876,91.186 172.974,91.186 v2(173.863,90.297)
PB8: OSC1.45
PB9: OSC1.46
PB12: OSC1.25 | length 5.2
  Top Layer w0.3: v2(136.017,107.061) 137.624,108.668 OSC1.25
PB13: OSC1.26 | length 4.1
  Top Layer w0.3: v2(136.906,106.934) 138.14,108.168 OSC1.26
PB14: OSC1.27 | length 3.1
  Top Layer w0.3: v2(137.795,106.807) 138.656,107.668 OSC1.27
PB15: OSC1.28 | length 1.9
  Top Layer w0.3: v2(138.811,106.807) 139.172,107.168 OSC1.28
PC13: OSC1.2
SWCLK: H1.3 OSC1.37 | length 25.1
  Top Layer w0.3: v2(134.874,100.965) 135.763,100.076 141.478,100.076 142.03,100.628 OSC1.37
  Bottom Layer w0.3: H1.3 134.112,107.823 134.874,107.061 v2(134.874,100.965)
SWDIO: H1.4 OSC1.34 | length 21.2
  Top Layer w0.3: v2(134.112,103.505) 134.775,104.168 OSC1.34
  Bottom Layer w0.3: H1.4 131.572,106.045 v2(134.112,103.505)
USB1CC1: R23.1 USB1.A5 | length 2.3
  Top Layer w0.3: USB1.A5 91.206,91.674 91.567,91.313 R23.1@91.83,91.313
USB1CC2: R24.1 USB1.B5 | length 2.7
  Top Layer w0.3: USB1.B5 91.087,88.674 91.83,89.417 R24.1@91.83,89.662
USB1D+: 
USB1D-: U4.2 USB1.A7 USB1.B7 | length 46.3
  Top Layer w0.3: USB1.A7 88.515,90.174 88.265,90.424 v2(88.265,90.932) 88.507,91.174 USB1.B7 ; v2(121.285,104.648) U4.2
  Bottom Layer w0.3: v2(88.265,90.932) 88.265,89.916 89.154,89.027 90.805,89.027 106.426,104.648 v2(121.285,104.648)
VCC: 3.3V指示灯.1 C13.2 C14.2 C15.2 C16.2 C17.2 C18.2 C19.1 C21.2 C23.1 C24.2 C25.1 C26.2 H1.1 OSC1.9 OSC1.24 OSC1.36 OSC1.48 R12.2 R13.2 R14.2 R15.1 R16.2 R17.1 R20.1 SW7.3 SW7.4 SW8.3 SW8.4 SW9.3 SW9.4 SW10.3 SW10.4 U2.2 U2.4 U3.8 U4.5 U4.8 U10.2 | length 348.5
  Top Layer w0.3: U4.5 129.856,102.108 C26.2 ; 130.429,94.488 150.876,94.488 154.37,97.982 ; C25.1 136.126,103.168 OSC1.36 ; 139.192,115.427 139.616,115.427 142.03,113.013 OSC1.24 ; H1.1 140.072,117.847 R12.2 ; OSC1.48 147.53,98.065 C21.2 154.37,97.982 ; OSC1.9 155.871,107.168 C23.1@155.947,107.244 ; R13.2 155.185,111.896 155.891,111.19 ; C24.2@169.102,116.205 164.087,111.19 155.891,111.19 ; 154.37,97.982 155.947,99.559 R17.1 C23.1@155.947,107.244 ; 155.891,111.19 C23.1 155.947,107.386 C23.1@155.947,107.244
  Top Layer w0.5: 126.599,109.285 128.143,107.741 128.143,106.314 U4.8 ; U10.2 169.102,116.205 C24.2 ; R20.1 187.715,127.254 206.756,127.254 v2(207.645,126.365) ; R14.2 211.328,113.783 211.328,117.72 ; R16.2 211.328,117.72 ; C18.2 211.328,123.174 211.328,117.72
  Top Layer w1: U2.2 U2.4 ; C14.2 118.094,96.22 C13.2 3.3V指示灯.1@120.43,94.488 ; 3.3V指示灯.1 3.3V指示灯.1@120.43,94.488 ; C26.2 126.599,97.073 ; C25.1 132.272,96.331 130.429,94.488 124.014,94.488 ; H1.1 139.192,115.427 139.192,113.411 138.303,112.522 128.143,112.522 126.599,110.978 126.599,109.285 126.599,97.073 ; SW7.4 SW7.4@183.516,85.699 ; v2(187.071,106.553) 187.071,87.757 185.013,85.699 SW7.4@183.516,85.699 ; U3.8 C18.2@210.17,124.332 ; v2(207.645,126.365) 208.28,127 209.485,127 C19.1 210.058,124.444 C18.2@210.17,124.332 ; C18.2 C18.2@210.17,124.332 ; U2.4 120.523,90.51 3.3V指示灯.1@120.523,94.488 ; U2.4 119.929,89.494 123.724,85.699 SW7.4@183.516,85.699 ; 3.3V指示灯.1@120.43,94.488 3.3V指示灯.1@120.523,94.488 ; 3.3V指示灯.1@120.523,94.488 124.014,94.488 ; 124.014,94.488 126.599,97.073
  Bottom Layer w1: v2(187.071,106.553) 206.883,126.365 v2(207.645,126.365)
VIN: C1.2 C2.2 C3.2 C11.2 C12.2 C27.1 H2.3 H3.3 R1.2 SW1.1 SW1.2 T1.1 U1.8 U2.3 U5.31 U5.32 U5.33 | length 176.7
  Top Layer w0.5: v2(132.334,134.493) 134.047,134.493 C27.1 136.499,134.558 U5.33 U5.32 U5.31
  Top Layer w0.69: C1.2 101.584,93.853 R1.2 102.554,94.036 C3.2 102.567,100.317 U1.8
  Top Layer w1: T1.1 94.004,105.284 94.004,100.306 100.06,94.25 C1.2 100.838,91.551 SW1.2 SW1.1 111.825,87.63 C12.2 111.935,87.616 U2.3 116.854,87.616 118.237,86.233 v2(120.269,86.233) ; v2(124.079,87.757) 129.159,92.837 159.429,92.837 ; H3.3 163.195,96.603 159.429,92.837 ; H2.3 175.895,96.468 172.264,92.837 159.429,92.837
  Bottom Layer w0.5: v2(124.079,87.757) 124.579,88.257 124.579,126.738 v2(132.334,134.493)
  Bottom Layer w1: v2(120.269,86.233) 122.555,86.233 v2(124.079,87.757)
VIPN: SW1.3 USB1.A4 USB1.A9 USB1.B4 USB1.B9 | length 34.5
  Top Layer w0.3: USB1.A9 SW1.3@95.894,87.874 ; USB1.B4 95.594,88.174 SW1.3@95.885,87.883 ; USB1.B9 94.905,92.674 95.885,91.694 SW1.3@95.885,87.883 ; USB1.A4 94.986,92.974 96.139,91.821 SW1.3 ; SW1.3 SW1.3@95.894,87.874 ; SW1.3@95.885,87.883 SW1.3@95.894,87.874
pads on no net: OSC1.1 OSC1.3 OSC1.4 OSC1.5 OSC1.6 T1.EMPTY U3.2 U3.5 U3.6 U3.7 U3.11 U3.13 U3.14 U3.17 U3.18 U3.19 U3.20 U3.21 U3.22 U4.1 U4.4 U5.36 U5.37 U5.38 U5.39 U5.41 U5.42 U5.43 U5.44 U5.45 U5.46 U5.47 U5.48 U5.49 U5.50 U5.51 U5.52 U5.53 U5.54 U5.55 U5.56 U5.57 U5.58 U5.59 U5.60 U5.61 U5.62 U6.11 U7.12 U8.2 U9.1 U10.1 U10.4 U10.5 U10.6 U10.7 U10.8 U10.9 U10.10 U10.11 U10.12 USB1.A6 USB1.A8 USB1.B6 USB1.B8
copper on no net: | length 41.8
  Top Layer w0.3: 89.664,89.674 90.606,89.674 90.783,89.851 v2(90.783,90.446) 90.555,90.674 89.664,90.674 ; v2(121.285,105.918) 123.175,105.918
  Bottom Layer w0.3: v2(90.783,90.446) 91.335,90.446 106.807,105.918 v2(121.285,105.918)

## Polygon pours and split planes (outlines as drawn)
$2N61153 on Top Layer (solid, remove dead copper): 98.044,107.95 109.982,107.95 109.982,118.364 98.044,118.364
$2N61152 on Top Layer (solid, remove dead copper, pour order 10): 82.804,107.95 97.409,107.95 97.409,118.364 82.804,118.364
$2N61152 on Bottom Layer (solid, remove dead copper, pour order 22): 82.804,107.95 97.409,107.95 97.409,129.032 82.804,129.032
$2N61153 on Bottom Layer (solid, remove dead copper, pour order 24): 98.044,109.093 109.982,109.093 109.982,118.364 98.044,118.364
$2N61145 on Top Layer (solid, remove dead copper, pour order 2): 104.14,107.569 103.886,107.315 103.886,104.267 104.14,104.013 105.537,104.013 105.918,103.632 105.918,103.218 106.139,102.997 107.188,102.997 107.315,103.124 107.315,104.521 106.934,104.902 106.934,106.697 106.588,107.042 106.588,107.28 106.299,107.569
$2N61148 on Top Layer (solid, remove dead copper, pour order 4): 107.569,107.315 107.188,106.934 107.188,105.283 108.331,104.14 111.76,104.14 112.268,104.648 112.268,106.934 111.887,107.315
GND on Top Layer (solid, remove dead copper, pour order 6): 107.315,107.188 117.094,116.967 117.094,125.857 118.618,127.381 212.852,127.381 217.297,122.936 217.297,80.899 212.598,76.2 82.804,76.2 76.2,82.804 76.2,103.505 79.883,107.188
GND on Bottom Layer (solid, remove dead copper, pour order 18): 117.094,125.857 118.618,127.381 212.852,127.381 217.297,122.936 217.297,80.899 212.598,76.2 82.804,76.2 76.2,82.804 76.2,103.505 79.883,107.188 110.871,107.188 117.094,113.411

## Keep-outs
Top Layer:
  region: 82.931,120.65 91.44,120.65 91.44,159.512 82.931,159.512
Board Outline Layer:
  lines w0.254: 81.788,85.163 ccw(c83.788,85.163) 83.788,83.163 211.788,83.163 ccw(c211.788,85.163) 213.788,85.163 213.788,95.91 213.051,96.647 191.262,96.647 189.865,98.044 189.865,107.696 191.262,109.093 213.604,109.093 213.788,109.277 213.788,159.163 ccw(c211.788,159.163) 211.788,161.163 83.788,161.163 ccw(c83.788,159.163) 81.788,159.163 81.788,85.163
Multi-Layer:
  circle w0.254: c84.788,101.163 r1.55
  circle w0.254: c210.788,146.163 r1.55
  circle w0.254: c210.788,86.163 r1.55
  circle w0.254: c84.788,101.163 r2.5
  circle w0.254: c210.788,86.163 r2.5
  circle w0.254: c210.788,146.163 r2.5

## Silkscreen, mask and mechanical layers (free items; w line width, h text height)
Top Silkscreen Layer:
  lines w0.254: 82.931,120.65 95.123,120.65 95.123,159.512 82.931,159.512 82.931,120.65
  text "高压危险，请勿触碰" at 84.328,152.4 h3.05 r270
  text "SWDIO/SWCLK/GND/VCC" at 125.857,118.618 h1.5
  text "GND/5V/U1TX/U1RX" at 157.353,99.187 h1.2
  text "GND/5V/TX2/RX2" at 171.958,99.187 h1.2
Top Solder Mask Layer:
  region: 88.519,116.078 88.519,118.364 82.804,118.364 82.804,107.95 91.02,107.95 91.02,111.213 91.694,111.887 97.409,111.887 97.409,118.364 92.506,118.364 92.506,116.001 91.948,115.443 89.154,115.443
  region: 100.838,107.95 98.044,107.95 98.044,118.364 109.982,118.364 109.982,116.301 103.601,116.301 103.251,115.951 103.251,111.125 103.124,110.998 101.219,110.998 100.838,110.617
Bottom Solder Mask Layer:
  region: 82.804,107.95 97.409,107.95 97.409,128.905 82.804,128.905
  region: 98.044,109.093 109.982,109.093 109.982,118.364 98.044,118.364
Mechanical Layer:
  circle w0.025: c84.788,101.163 r1.55
  circle w0.025: c210.788,146.163 r1.55
  circle w0.025: c210.788,86.163 r1.55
